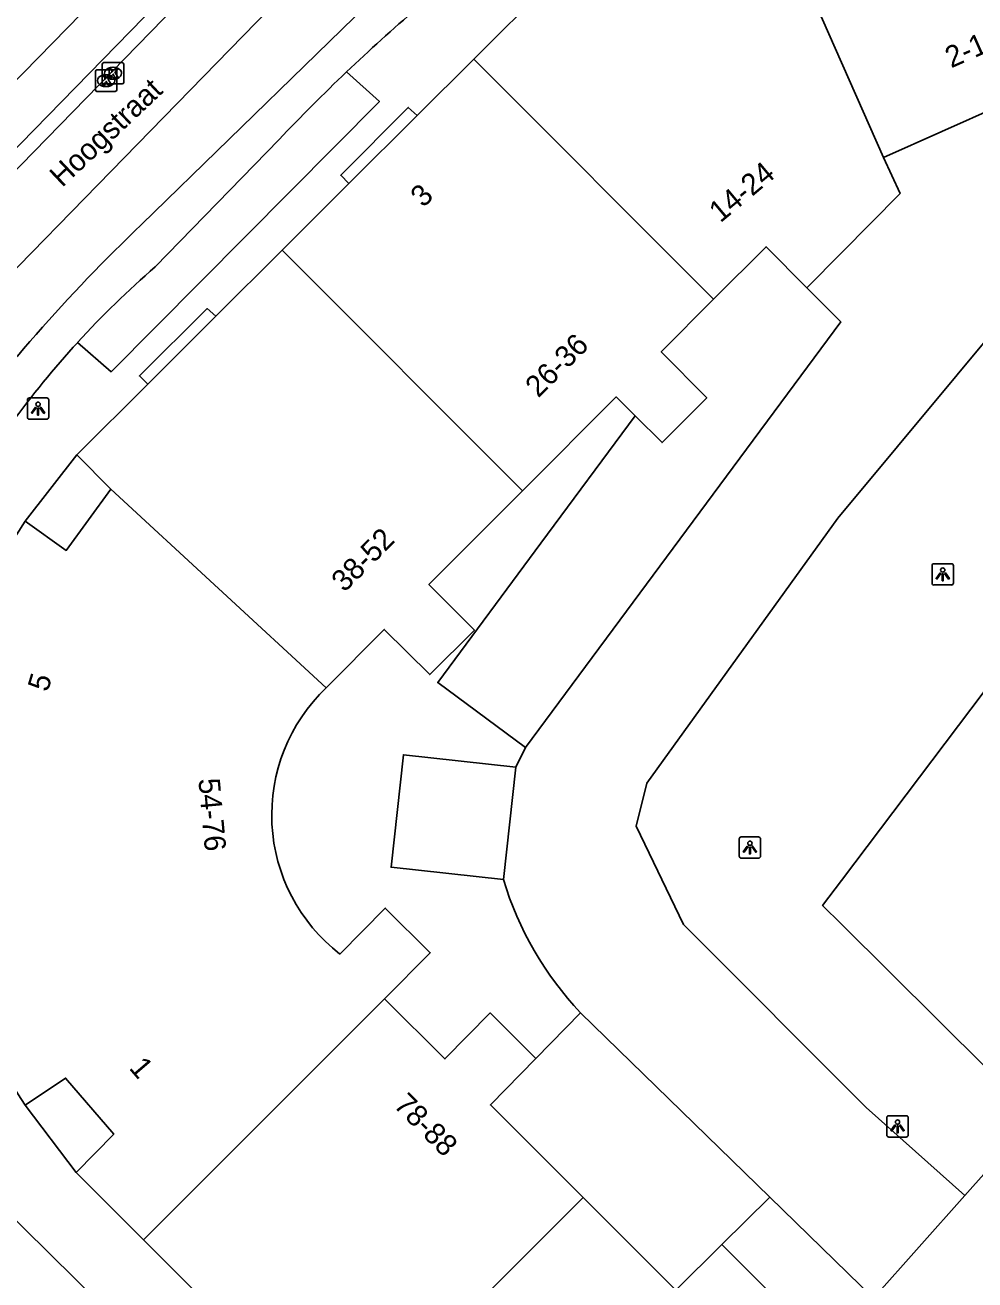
# Model space of a CAD drawing. Extents: x 160664 to 161506, y 382245 to 383288.
# Drawn here: x 160961.9 to 161006.2, y 382839.9 to 382898.5 of the extents above; entities that cross this region are included whole.
import ezdxf

# ---------------------------------------------------------------- set-up
doc = ezdxf.new("R2010")
doc.units = 0
for name, color, linetype in [('IMGEO_Fietspad_gesloten', 7, 'Continuous'), ('IMGEO_Kolk', 7, 'Continuous'), ('IMGEO_Lichtpunt', 7, 'Continuous'), ('IMGEO_Openbare_ruimte_label', 7, 'Continuous'), ('IMGEO_OVBaan_gesloten', 7, 'Continuous'), ('IMGEO_Pand', 7, 'Continuous'), ('IMGEO_Pand_nummerreeks', 7, 'Continuous'), ('IMGEO_Rijbaan_lokaal_gesloten', 7, 'Continuous'), ('IMGEO_Rijbaan_lokaal_open', 7, 'Continuous'), ('IMGEO_Voetpad_open', 7, 'Continuous')]:
    doc.layers.add(name, color=color, linetype=linetype)

msp = doc.modelspace()

# ---------------------------------------------------------------- linework, layer by layer
at = {"layer": 'IMGEO_Fietspad_gesloten'}
for points in [[(160974.65, 382909.428), (160938.834, 382872.783)], [(160941.196, 382871.992), (160975.751, 382907.414)], [(160958.18, 382845.894), (160985.945, 382818.488)]]:
    msp.add_lwpolyline(points, dxfattribs=at)
at = {"layer": 'IMGEO_Kolk'}
for p, q in [((160965.243, 382896.41), (160966.095, 382896.41)), ((160965.491, 382895.829), (160965.491, 382896.681)), ((160965.566, 382896.755), (160966.418, 382896.755)), ((160965.979, 382896.535), (160966.004, 382896.535)), ((160966.492, 382896.681), (160966.492, 382895.829)), ((160965.168, 382895.484), (160965.168, 382896.336)), ((160965.656, 382896.19), (160965.681, 382896.19)), ((160966.002, 382895.975), (160965.977, 382895.975)), ((160966.169, 382896.336), (160966.169, 382895.484)), ((160966.095, 382895.41), (160965.243, 382895.41)), ((160966.418, 382895.755), (160965.566, 382895.755)), ((160965.679, 382895.63), (160965.654, 382895.63))]:
    msp.add_line(p, q, dxfattribs=at)
for points in [[(160965.243, 382896.41), (160966.095, 382896.41)], [(160965.491, 382895.829), (160965.491, 382896.681)], [(160965.566, 382896.755), (160966.418, 382896.755)], [(160965.812, 382896.455), (160965.935, 382896.455), (160965.935, 382896.304), (160966.065, 382896.455), (160966.229, 382896.455), (160966.083, 382896.304), (160966.236, 382896.055), (160966.084, 382896.055), (160965.999, 382896.219), (160965.935, 382896.152), (160965.935, 382896.055), (160965.812, 382896.055), (160965.812, 382896.455)], [(160966.492, 382896.681), (160966.492, 382895.829)], [(160965.168, 382895.484), (160965.168, 382896.336)], [(160965.489, 382896.11), (160965.612, 382896.11), (160965.612, 382895.959), (160965.742, 382896.11), (160965.906, 382896.11), (160965.76, 382895.959), (160965.913, 382895.71), (160965.761, 382895.71), (160965.676, 382895.874), (160965.612, 382895.807), (160965.612, 382895.71), (160965.489, 382895.71), (160965.489, 382896.11)], [(160966.169, 382896.336), (160966.169, 382895.484)], [(160966.095, 382895.41), (160965.243, 382895.41)], [(160966.418, 382895.755), (160965.566, 382895.755)]]:
    msp.add_lwpolyline(points, dxfattribs=at)
for centre, start, end in [((160965.245, 382896.334), 91.55205, 178.44795), ((160965.245, 382896.334), 91.55205, 178.44795), ((160965.568, 382896.679), 91.55205, 178.44795), ((160965.568, 382896.679), 91.55205, 178.44795), ((160966.093, 382896.334), 1.55205, 88.44795), ((160966.093, 382896.334), 1.55205, 88.44795), ((160966.416, 382896.679), 1.55205, 88.44795), ((160966.416, 382896.679), 1.55205, 88.44795), ((160965.568, 382895.831), 181.55205, 268.44795), ((160965.568, 382895.831), 181.55205, 268.44795), ((160966.416, 382895.831), 271.55205, 358.44795), ((160966.416, 382895.831), 271.55205, 358.44795), ((160965.245, 382895.486), 181.55205, 268.44795), ((160965.245, 382895.486), 181.55205, 268.44795), ((160966.093, 382895.486), 271.55205, 358.44795), ((160966.093, 382895.486), 271.55205, 358.44795)]:
    msp.add_arc(centre, 0.0765, start, end, dxfattribs=at)
for centre, major_axis, ratio, start_param, end_param in [((160965.978, 382896.255), (-0.387, 0.002), 0.722429, 4.712389, 7.853982), ((160966.003, 382896.255), (-0.39, 0.002), 0.717154, 1.570796, 4.712389), ((160965.655, 382895.91), (-0.387, 0.002), 0.722429, 4.712389, 7.853982), ((160965.68, 382895.91), (-0.39, 0.002), 0.717154, 1.570796, 4.712389)]:
    msp.add_ellipse(centre, major_axis=major_axis, ratio=ratio, start_param=start_param, end_param=end_param, dxfattribs=at)
at = {"layer": 'IMGEO_Lichtpunt'}
for p, q in [((160961.992, 382880.998), (160961.992, 382880.191)), ((160961.992, 382880.998), (160961.992, 382880.191)), ((160962.894, 382881.093), (160962.086, 382881.093)), ((160962.894, 382881.093), (160962.086, 382881.093)), ((160962.988, 382880.191), (160962.988, 382880.998)), ((160962.988, 382880.191), (160962.988, 382880.998)), ((160962.086, 382880.097), (160962.894, 382880.097)), ((160962.086, 382880.097), (160962.894, 382880.097)), ((161004.233, 382873.254), (161004.233, 382872.447)), ((161004.233, 382873.254), (161004.233, 382872.447)), ((161005.135, 382873.349), (161004.327, 382873.349)), ((161005.135, 382873.349), (161004.327, 382873.349)), ((161005.229, 382872.447), (161005.229, 382873.254)), ((161005.229, 382872.447), (161005.229, 382873.254)), ((161004.327, 382872.353), (161005.135, 382872.353)), ((161004.327, 382872.353), (161005.135, 382872.353)), ((160995.228, 382860.495), (160995.228, 382859.688)), ((160995.228, 382860.495), (160995.228, 382859.688)), ((160996.13, 382860.59), (160995.322, 382860.59)), ((160996.13, 382860.59), (160995.322, 382860.59)), ((160996.224, 382859.688), (160996.224, 382860.495)), ((160996.224, 382859.688), (160996.224, 382860.495)), ((160995.322, 382859.594), (160996.13, 382859.594)), ((160995.322, 382859.594), (160996.13, 382859.594)), ((161002.121, 382847.47), (161002.121, 382846.663)), ((161002.121, 382847.47), (161002.121, 382846.663)), ((161003.023, 382847.565), (161002.215, 382847.565)), ((161003.023, 382847.565), (161002.215, 382847.565)), ((161003.117, 382846.663), (161003.117, 382847.47)), ((161003.117, 382846.663), (161003.117, 382847.47)), ((161002.215, 382846.569), (161003.023, 382846.569)), ((161002.215, 382846.569), (161003.023, 382846.569))]:
    msp.add_line(p, q, dxfattribs=at)
for points in [[(160962.366, 382880.662), (160962.405, 382880.634), (160962.217, 382880.372), (160962.179, 382880.399), (160962.366, 382880.662)], [(160962.468, 382880.614), (160962.515, 382880.614), (160962.515, 382880.292), (160962.468, 382880.292), (160962.468, 382880.614)], [(160962.578, 382880.634), (160962.616, 382880.661), (160962.803, 382880.399), (160962.764, 382880.371), (160962.578, 382880.634)], [(161004.607, 382872.918), (161004.646, 382872.89), (161004.458, 382872.628), (161004.42, 382872.655), (161004.607, 382872.918)], [(161004.819, 382872.89), (161004.857, 382872.917), (161005.044, 382872.655), (161005.005, 382872.627), (161004.819, 382872.89)], [(161004.709, 382872.87), (161004.756, 382872.87), (161004.756, 382872.548), (161004.709, 382872.548), (161004.709, 382872.87)], [(160995.602, 382860.159), (160995.641, 382860.131), (160995.453, 382859.869), (160995.415, 382859.896), (160995.602, 382860.159)], [(160995.704, 382860.111), (160995.751, 382860.111), (160995.751, 382859.789), (160995.704, 382859.789), (160995.704, 382860.111)], [(160995.814, 382860.131), (160995.852, 382860.158), (160996.039, 382859.896), (160996, 382859.868), (160995.814, 382860.131)], [(161002.495, 382847.134), (161002.534, 382847.106), (161002.346, 382846.844), (161002.308, 382846.871), (161002.495, 382847.134)], [(161002.707, 382847.106), (161002.745, 382847.133), (161002.932, 382846.871), (161002.893, 382846.843), (161002.707, 382847.106)], [(161002.597, 382847.086), (161002.644, 382847.086), (161002.644, 382846.764), (161002.597, 382846.764), (161002.597, 382847.086)]]:
    msp.add_lwpolyline(points, dxfattribs=at)
for centre in [(160962.491, 382880.796), (161004.732, 382873.052), (160995.727, 382860.293), (161002.62, 382847.268)]:
    msp.add_circle(centre, 0.0994, dxfattribs=at)
for centre, start, end in [((160962.086, 382880.998), 90, 180), ((160962.086, 382880.998), 90, 180), ((160962.894, 382880.998), 0, 90), ((160962.894, 382880.998), 0, 90), ((160962.086, 382880.191), 180, 270), ((160962.086, 382880.191), 180, 270), ((160962.894, 382880.191), 270, 0), ((160962.894, 382880.191), 270, 360), ((161004.327, 382873.254), 90, 180), ((161004.327, 382873.254), 90, 180), ((161005.135, 382873.254), 0, 90), ((161005.135, 382873.254), 0, 90), ((161004.327, 382872.447), 180, 270), ((161004.327, 382872.447), 180, 270), ((161005.135, 382872.447), 270, 0), ((161005.135, 382872.447), 270, 360), ((160995.322, 382860.495), 90, 180), ((160995.322, 382860.495), 90, 180), ((160996.13, 382860.495), 0, 90), ((160996.13, 382860.495), 0, 90), ((160995.322, 382859.688), 180, 270), ((160995.322, 382859.688), 180, 270), ((160996.13, 382859.688), 270, 0), ((160996.13, 382859.688), 270, 360), ((161002.215, 382847.47), 90, 180), ((161002.215, 382847.47), 90, 180), ((161003.023, 382847.47), 0, 90), ((161003.023, 382847.47), 0, 90), ((161002.215, 382846.663), 180, 270), ((161002.215, 382846.663), 180, 270), ((161003.023, 382846.663), 270, 0), ((161003.023, 382846.663), 270, 360)]:
    msp.add_arc(centre, 0.0946, start, end, dxfattribs=at)
at = {"layer": 'IMGEO_OVBaan_gesloten'}
for points in [[(160948.009, 382873.34), (160978.235, 382904.348), (160983.292, 382909.484), (160980.971, 382911.704)], [(160976.231, 382906.892), (160941.719, 382871.483)]]:
    msp.add_lwpolyline(points, dxfattribs=at)
at = {"layer": 'IMGEO_Pand'}
for points in [[(161001.969, 382892.326), (160995.558, 382906.855)], [(160986.346, 382900.425), (160982.835, 382896.922)], [(161014.607, 382897.256), (161014.294, 382897.128), (161014.052, 382897.682), (161010.131, 382895.912), (161011.314, 382893.149), (161008.614, 382891.962), (161007.416, 382894.745), (161001.969, 382892.326)], [(160982.835, 382896.922), (160980.188, 382894.281)], [(160982.835, 382896.922), (160994.035, 382885.697)], [(160980.188, 382894.281), (160977.005, 382891.107)], [(160998.387, 382886.24), (161000, 382887.874), (161002.736, 382890.646), (161001.969, 382892.326)], [(160977.005, 382891.107), (160973.89, 382887.999)], [(160994.035, 382885.697), (160996.482, 382888.155), (160998.387, 382886.24)], [(160973.89, 382887.999), (160970.791, 382884.908)], [(160985.107, 382876.755), (160973.89, 382887.999)], [(160990.367, 382880.253), (160991.626, 382879.003), (160993.715, 382881.096), (160991.588, 382883.238), (160994.035, 382885.697)], [(160970.791, 382884.908), (160967.611, 382881.736)], [(160967.611, 382881.736), (160964.3, 382878.433)], [(160990.367, 382880.253), (160989.476, 382881.138), (160985.107, 382876.755)], [(160964.3, 382878.433), (160965.895, 382876.832)], [(160965.895, 382876.832), (160963.81, 382873.968), (160961.894, 382875.336)], [(160975.944, 382867.549), (160965.895, 382876.832)], [(160985.107, 382876.755), (160980.737, 382872.371), (160982.865, 382870.246), (160980.779, 382868.166), (160978.655, 382870.281), (160975.944, 382867.549)], [(160978.671, 382853.029), (160980.8, 382855.176), (160978.705, 382857.265), (160976.581, 382855.116)], [(160967.417, 382841.771), (160978.671, 382853.029)], [(160978.671, 382853.029), (160981.485, 382850.215), (160983.6, 382852.365), (160985.729, 382850.234)], [(160987.939, 382843.74), (160983.615, 382848.065), (160985.729, 382850.234)], [(160961.887, 382848.056), (160963.774, 382849.325), (160966.024, 382846.702), (160964.276, 382844.911)], [(161005.762, 382843.842), (161009.04, 382847.522)], [(160964.276, 382844.911), (160967.417, 382841.771)], [(160976.696, 382832.495), (160987.939, 382843.74)], [(160994.42, 382841.542), (160992.264, 382839.415), (160987.939, 382843.74)], [(161001.492, 382839.047), (161005.762, 382843.842)], [(160970.438, 382838.751), (160967.417, 382841.771)], [(160997.101, 382834.576), (160994.393, 382837.303), (160996.522, 382839.439), (160994.42, 382841.542)]]:
    msp.add_lwpolyline(points, dxfattribs=at)
for centre, radius, start, end in [((160982.929, 382861.691), 25.073, 147.02951, 201.55824), ((160981.619, 382861.607), 8.217, 133.68209, 232.18383), ((160982.805, 382861.624), 24.933, 201.52074, 212.96943)]:
    msp.add_arc(centre, radius, start, end, dxfattribs=at)
at = {"layer": 'IMGEO_Rijbaan_lokaal_gesloten'}
for points in [[(160967.323, 382889.193), (160979.605, 382901.159), (160988.644, 382908.245)], [(160967.964, 382887.219), (160973.745, 382893.156)]]:
    msp.add_lwpolyline(points, dxfattribs=at)
for centre, radius, start, end in [((161035.434, 382834.86), 84.877, 127.63429, 133.60625), ((161035.453, 382834.852), 84.896, 133.61145, 136.62452), ((161022.995, 382830.885), 80.617, 133.6752, 143.79143), ((160997.111, 382853.705), 44.416, 131.01371, 137.54516), ((161000.498, 382850.845), 48.845, 137.75169, 149.3078)]:
    msp.add_arc(centre, radius, start, end, dxfattribs=at)
at = {"layer": 'IMGEO_Rijbaan_lokaal_open'}
for points in [[(161009.04, 382847.522), (161000, 382856.514), (160999.119, 382857.39), (161000, 382858.557), (161023.576, 382889.795), (161019.667, 382893.047)], [(160998.387, 382886.24), (160999.972, 382884.647), (160985.243, 382864.763)], [(161009.918, 382884.242), (161008.193, 382885.524), (160999.832, 382875.47), (160993.888, 382867.215), (160990.918, 382863.091), (160990.417, 382861.086), (160992.626, 382856.489), (161001.149, 382847.95), (161005.762, 382843.842)], [(160984.802, 382863.844), (160985.243, 382864.763)], [(160984.802, 382863.844), (160984.224, 382858.592)], [(160987.817, 382852.376), (160996.662, 382843.754)], [(160996.662, 382843.754), (161001.492, 382839.047)]]:
    msp.add_lwpolyline(points, dxfattribs=at)
msp.add_arc((160999.09, 382863.039), 15.517, 196.65236, 223.40556, dxfattribs=at)
at = {"layer": 'IMGEO_Voetpad_open'}
for points in [[(160976.895, 382896.319), (160978.43, 382894.941), (160965.899, 382882.312), (160964.341, 382883.686)], [(160977.005, 382891.107), (160976.622, 382891.494), (160979.774, 382894.66), (160980.188, 382894.281)], [(160967.611, 382881.736), (160967.222, 382882.121), (160970.381, 382885.266), (160970.791, 382884.908)], [(160985.243, 382864.763), (160981.154, 382867.792), (160985.973, 382874.309), (160990.367, 382880.253)], [(160961.894, 382875.336), (160964.3, 382878.433)], [(160984.224, 382858.592), (160978.974, 382859.17), (160979.552, 382864.422), (160984.802, 382863.844)], [(160985.729, 382850.234), (160987.817, 382852.376)], [(160964.276, 382844.911), (160961.887, 382848.056)], [(160996.662, 382843.754), (160994.42, 382841.542)]]:
    msp.add_lwpolyline(points, dxfattribs=at)

# ---------------------------------------------------------------- texts
at = {"layer": 'IMGEO_Openbare_ruimte_label'}
msp.add_text('Hoogstraat', height=1, rotation=43.33796, dxfattribs=at).set_placement((160963.614, 382890.892))
at = {"layer": 'IMGEO_Pand_nummerreeks'}
for s, rotation, p in [('2-12', 23.90615, (161005.127, 382896.482)), ('14-24', 39.88149, (160994.349, 382889.243)), ('3', 44.92562, (160980.486, 382889.947)), ('26-36', 45.04594, (160985.847, 382881.063)), ('38-52', 45.13413, (160976.798, 382871.979)), ('5', 73.51049, (160962.943, 382867.324)), ('54-76', 275.28819, (160969.974, 382863.286)), ('1', 310.6225, (160966.706, 382849.776)), ('78-88', 314.93671, (160979.046, 382848.009))]:
    msp.add_text(s, height=1, rotation=rotation, dxfattribs=at).set_placement(p)

doc.saveas('drawing.dxf')
